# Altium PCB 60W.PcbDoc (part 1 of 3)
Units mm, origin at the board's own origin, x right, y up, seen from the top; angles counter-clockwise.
Board outline 118.9 x 83.5 mm, 3 copper layers (Top Layer, Mid-Layer 2, Bottom Layer); 99 components, 61 nets, 240 pads, 0 vias.
Unrouted connection lines stored in the file: 1.
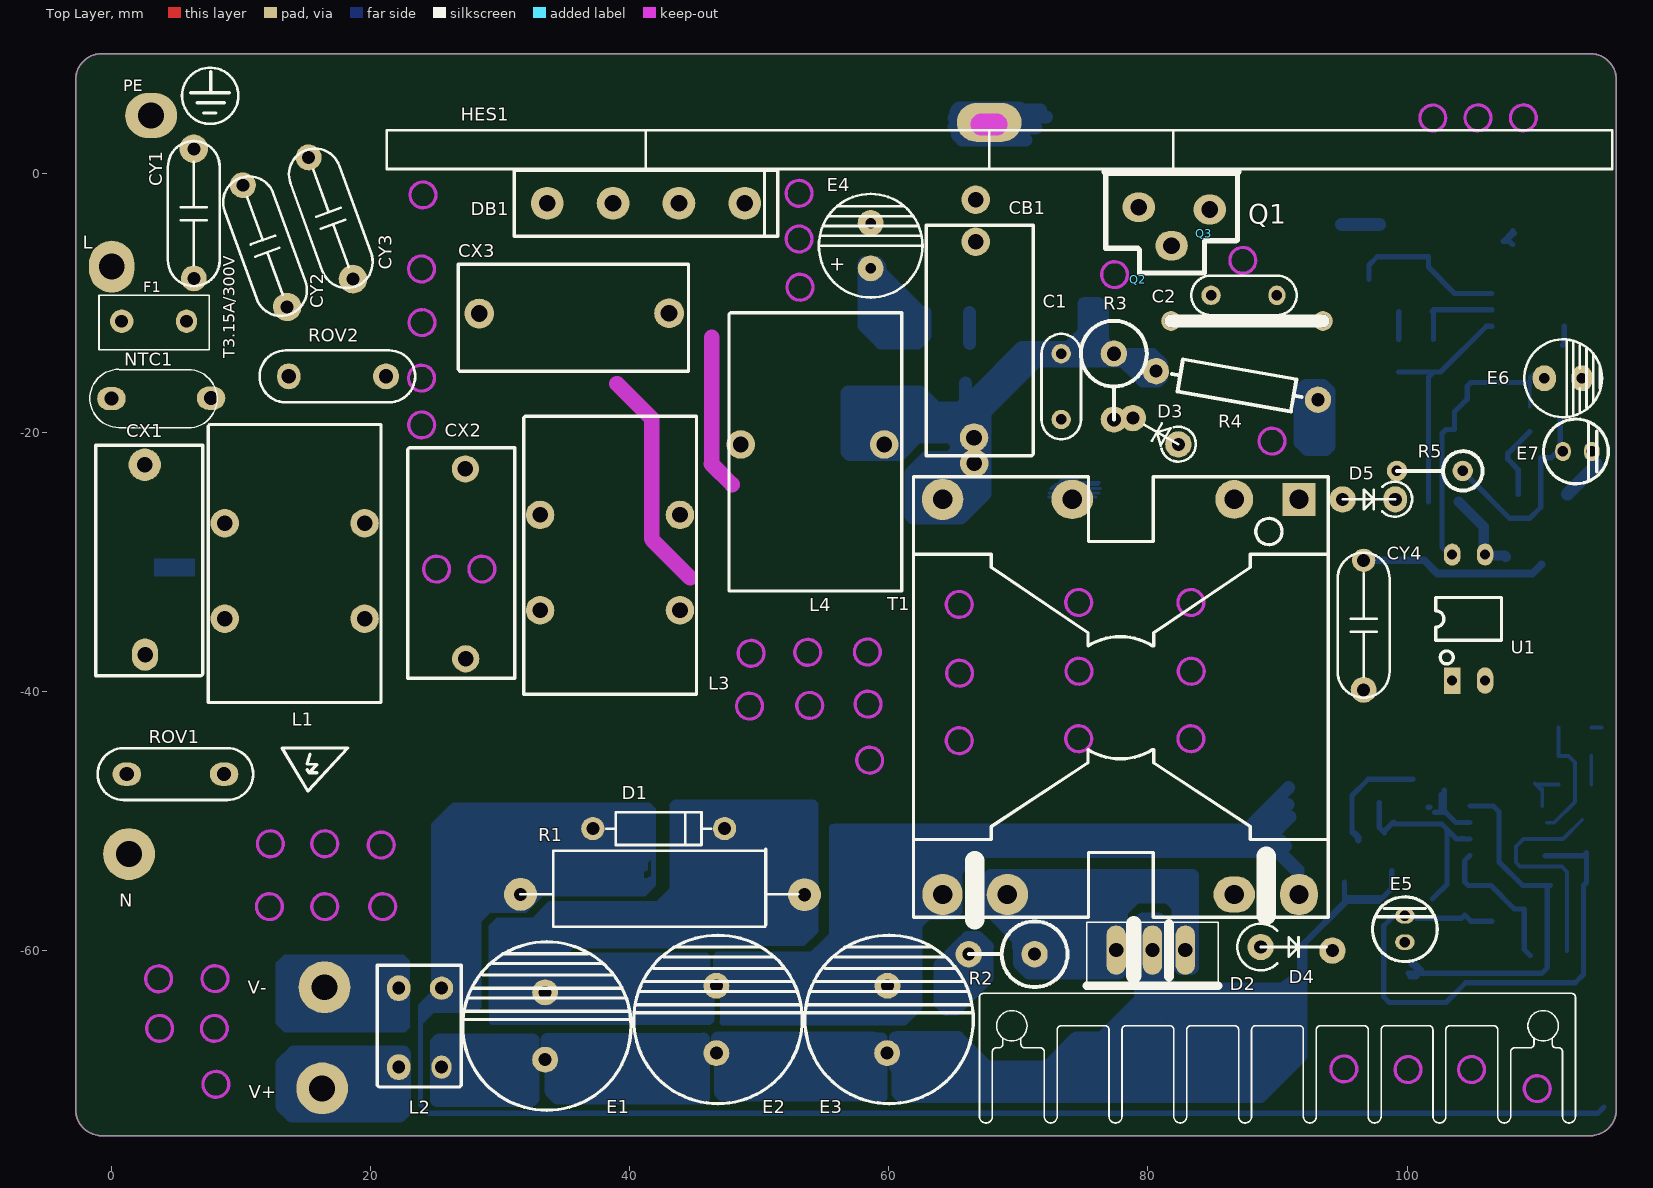
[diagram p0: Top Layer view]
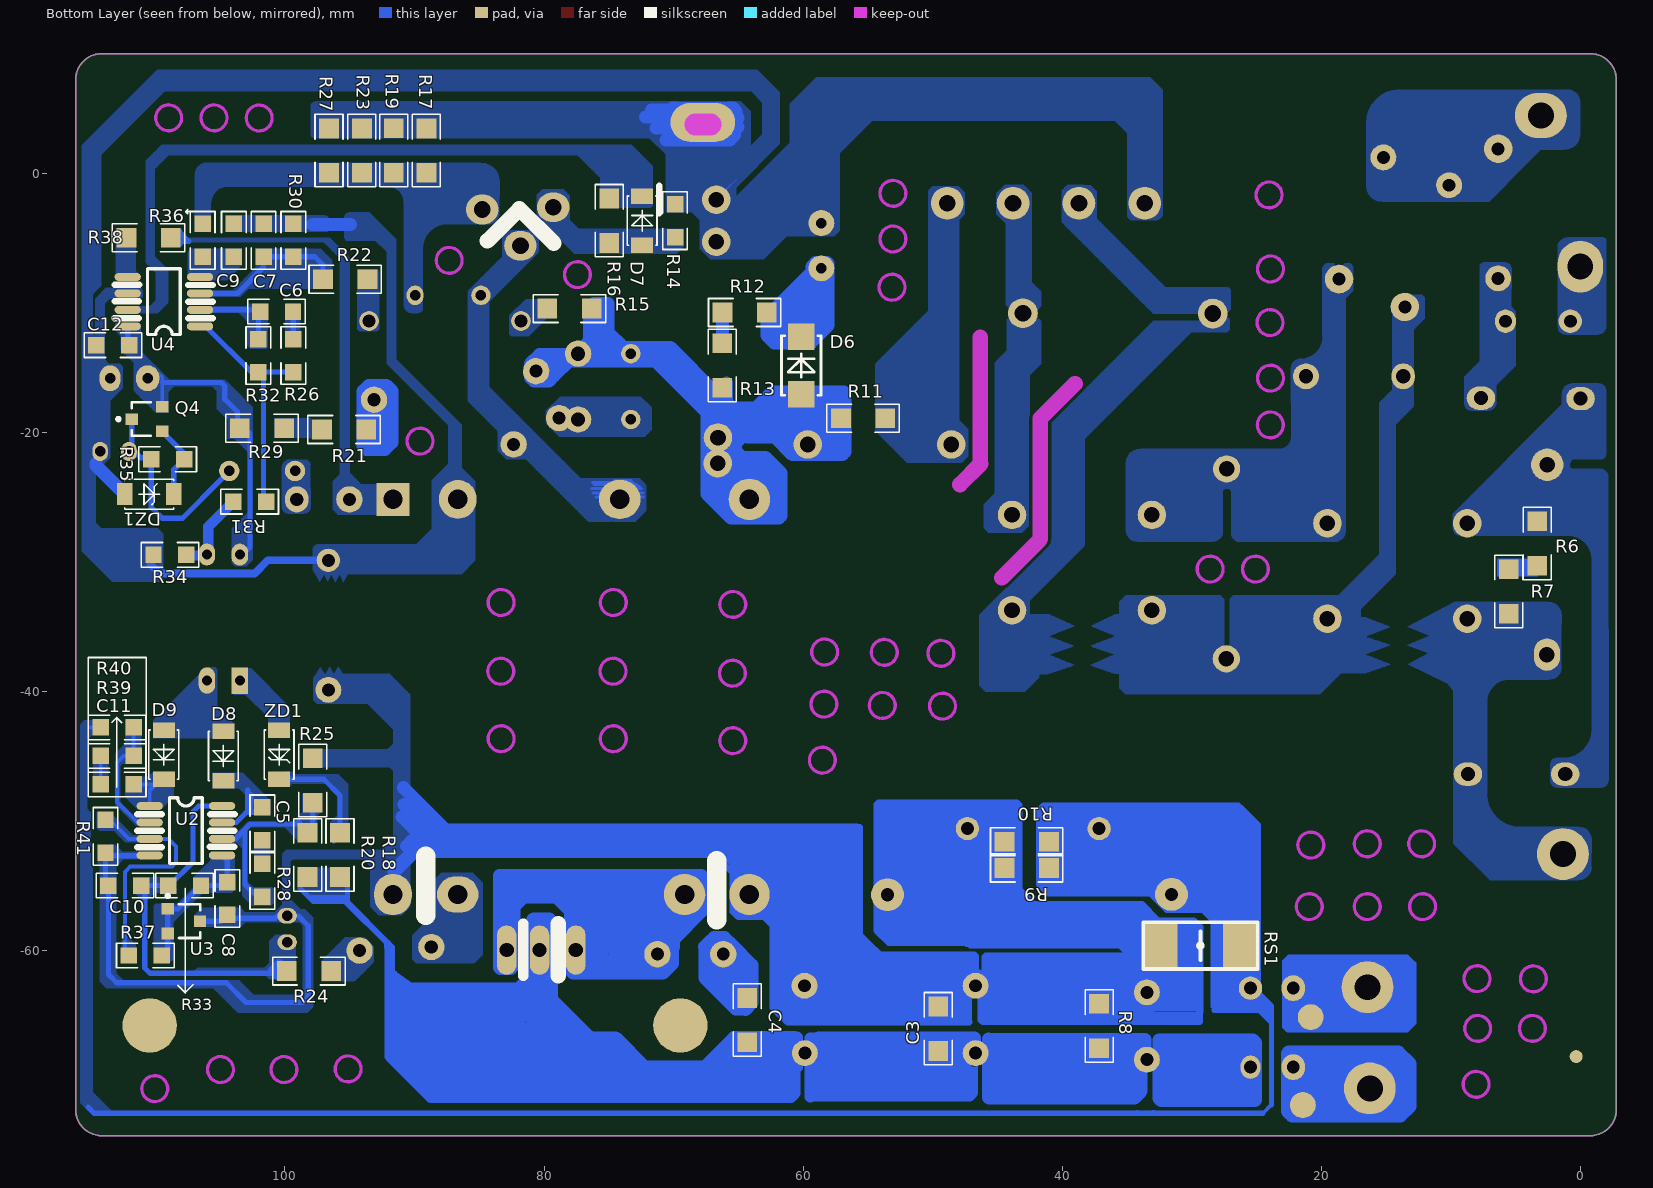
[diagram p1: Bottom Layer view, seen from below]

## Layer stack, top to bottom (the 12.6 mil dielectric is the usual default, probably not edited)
Top Layer: signal copper 0.0356
Dielectric: dielectric 0.32, FR-4, Dk 4.8
Mid-Layer 2: signal copper 0.0356
Dielectric: dielectric 0.32, FR-4, Dk 4.8
Bottom Layer: signal copper 0.0356

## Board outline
-2.75,-72.25 -2.75,7.25 cw(c-0.75,7.25) -0.75,9.25 114.15,9.25 cw(c114.15,7.25) 116.15,7.25 116.15,-72.25 cw(c114.15,-72.25) 114.15,-74.25 -0.75,-74.25 cw(c-0.75,-72.25)

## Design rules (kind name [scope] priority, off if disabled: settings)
Clearance [All] p1: gap=0.254
PolygonConnect [All] p1: connectstyle=Direct reliefconductorwidth=0.254 reliefentries=4 polygonreliefangle="90 Angle"
RoutingVias [All] p1: holewidth=0.711 width=1.27 viastyle="Through Hole" minholewidth=0.711 minwidth=1.27 maxholewidth=0.711 maxwidth=1.27
SilkscreenOverComponentPads [All] p1: minsilkscreentomaskgap=0.254
SolderMaskExpansion [All] p1: expansion=0.102
TestPointUsage [All] p1: valid=0 allowmultiple=FALSE
Testpoint [All] p1: side=15 testpointundercomponent=TRUE minsize=1.016 maxsize=2.54 preferedsize=1.524 minholesize=0 maxholesize=1.016 preferedholesize=0.813 testpointgrid=0.025 style=1023 order=0123456789
Width [All] p1: maxlimit=7.62 minlimit=0.254 preferedwidth=0.254 toplayer_prefwidth=0.406 midlayer2_maxwidth=0.254 bottomlayer_prefwidth=0.406 minimp=50.000000 maximp=50.000000 favimp=50.000000
23 further rules are at their usual default settings.

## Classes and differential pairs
component class PD0020: C3 C4 C5 C6 C7 C8 C9 C10 C11 C12 CY3 CY4 D2 D3 D4 D5 D7 D8 D9 DB1 DZ1 E2 E3 E5 E6 E7 F1 L2 L3 NTC1 Q1 R1 R2 R3 R5 R6 R7 R8 R9 R14 R15 R16 R17 R18 R20 R21 R22 R23 R25 R26 R27 R30 R31 R32 R33 R34 R36 R37 R38 R39 R40 R41 R47 ROV2 T1 U1 U2 U3 U4 ZD1

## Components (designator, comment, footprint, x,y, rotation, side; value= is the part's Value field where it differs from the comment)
C1 "103/1KV" CAP200#1 73.311,-13.9 r270 top (schematic designator C2)
C2 "103/1KV" CAP200#2 84.875,-9.4 r0 top
C3 "0.1uF/100V" 1206 49.588,-65.995 r90 bottom (schematic designator C10)
C4 "221/1KV" 1206 64.319,-65.335 r270 bottom (schematic designator C7)
C5 "0.1uF/50V" 0805 101.75,-50.18 r90 bottom (schematic designator C15)
C6 "0.1uF/50V" 0805 100.65,-10.65 r180 bottom
C7 "102" 0805 101.65,-5.15 r270 bottom (schematic designator C5)
C8 "0.1uF/50V" 0805 104.45,-55.95 r90 bottom (schematic designator C14)
C9 "68pf" 0805 103.944,-5.15 r90 bottom (schematic designator C16)
C10 "0.1uF/50V" 0805 112.35,-54.95 r0 bottom (schematic designator C12)
C11 "0.1uF/50V" 0805 112.95,-47.15 r180 bottom (schematic designator C13)
C12 "104" 0805 113.28,-13.25 r180 bottom (schematic designator C4)
CB1 "Comment" PCBComponent_1#1 71.152,-3.995 r270 top
CX1 "Comment" PCBComponent_1#2 7.05,-20.975 r270 top
CX2 "Comment" PCBComponent_1#3 22.88,-38.949 r90 top
CX3 "Comment" PCBComponent_1#4 44.55,-15.25 r180 top
CY1 "Cap" Y#1 6.375,-8.1 r90 top (schematic designator C21)
CY2 "Cap" Y#1 10.139,-0.897 r290 top (schematic designator C21)
CY3 "Cap" Y#1 15.217,1.253 r290 top (schematic designator C20)
CY4 "222/400VAC" Y#2 96.64,-29.84 r270 top (schematic designator CY1)
D1 "Comment" DIODE-0.4 42.247,-50.552 r0 top
D2 "3N80" TO220M 80.347,-59.933 r180 top (schematic designator Q1)
D3 "FR107" DO-41_120 82.35,-20.9 r150 top (schematic designator D1)
D4 "FR107" DO-15_200 88.704,-59.696 r0 top (schematic designator D5)
D5 "FR107" DO-41_160 95.025,-25.15 r0 top (schematic designator D2)
D6 "D" SMA214 60.154,-14.814 r90 bottom (schematic designator D3)
D7 "D" LL-34 72.434,-3.638 r90 bottom (schematic designator D3)
D8 "" LL-34 104.75,-44.95 r270 bottom (schematic designator D6)
D9 "D" LL-34 109.35,-44.85 r270 bottom (schematic designator D7)
DB1 "DF107" DB-L200 41.265,-2.292 r180 top locked
DZ1 "DIODE_ZENER" LL-34_Z 110.475,-24.75 r180 bottom
E1 "Comment" "PCBComponent_1 - duplicate4"#1 33.611,-65.792 r270 top
E2 "Comment" "PCBComponent_1 - duplicate4"#1 46.819,-65.284 r270 top
E3 "Comment" "PCBComponent_1 - duplicate4"#2 60.027,-65.284 r270 top
E4 "Comment" CE8 58.604,-5.569 r90 top
E5 "47uF/35V" CE05#1 99.834,-58.305 r90 top (schematic designator C11)
E6 "Comment" CE6 112.05,-15.8 r0 top
E7 "10UF/50V" CE05#2 113.05,-21.45 r0 top (schematic designator C3)
F1 "Comment" "FUSE 3.15A/300VAC" 3.3,-11.5 r90 top
HES1 "Comment" "HES1  97*50MM" 21.25,0.35 r0 top locked
L1 "20MH" PCBComponent_1#5 18.15,-19.364 r180 top (schematic designator L3)
L2 "Comment" "PCBComponent_1 - duplicate1" 27.007,-70.364 r90 top
L3 "20MH" PCBComponent_1#5 42.49,-18.726 r180 top
L4 "20MH" PCBComponent_1#6 58.337,-10.75 r180 top (schematic designator L3)
NTC1 "1A/10R" NTC 0,-17.375 r0 top
Q1 "Comment" T-220品字 81.829,-2.622 r0 top locked
Q2 "Comment" PCBComponent_1#7 79.255,-8.21 r270 top
Q3 "Comment" PCBComponent_1#7 84.335,-4.654 r270 top
Q4 "Comment" SOT23 110.65,-18.95 r90 bottom
R1 "0.1R" RESQ5W 31.579,-55.632 r0 top (schematic designator R28)
R2 "100R" RES200#1 71.254,-60.25 r180 top (schematic designator R21)
R3 "100K" RES200#2 77.375,-13.9 r270 top (schematic designator R1)
R4 "100K" RES500 80.616,-15.251 r350 top (schematic designator R1)
R5 "20R" RES200S 104.301,-22.95 r180 top (schematic designator R7)
R6 "1M" 1206 3.35,-28.55 r90 bottom (schematic designator R20)
R7 "1M" 1206 5.55,-32.25 r90 bottom (schematic designator R19)
R8 "res1" 1206 37.167,-65.792 r270 bottom (schematic designator R22)
R9 "OPEN" 1206 42.755,-53.6 r0 bottom (schematic designator R23)
R10 "OPEN" 1206 42.755,-51.568 r0 bottom (schematic designator R23)
R11 "res1" 1206 55.379,-18.878 r0 bottom (schematic designator R22)
R12 "res1" 1206 64.523,-10.725 r180 bottom (schematic designator R22)
R13 "res1" 1206 66.25,-14.814 r90 bottom (schematic designator R22)
R14 "1.5M" 0805 69.894,-3.638 r270 bottom (schematic designator R2)
R15 "1.5M" 1206 78.036,-10.42 r180 bottom (schematic designator R2)
R16 "res1" 1206 74.974,-3.638 r90 bottom (schematic designator R8)
R17 "3.6R" 1206 89.085,1.772 r270 bottom (schematic designator R16)
R18 "res1" 1206 95.75,-52.584 r270 bottom (schematic designator R22)
R19 "3.6R" 1206 91.599,1.772 r270 bottom (schematic designator R16)
R20 "120K" 1206 98.25,-52.584 r270 bottom (schematic designator R29)
R21 "1M" 1206 95.435,-19.75 r180 bottom (schematic designator R6)
R22 "1.5M" 1206 95.35,-8.15 r180 bottom (schematic designator R3)
R23 "3.6R" 1206 94.063,1.772 r270 bottom (schematic designator R18)
R24 "res1" 1206 98.15,-61.55 r180 bottom (schematic designator R22)
R25 "10K" 1206 97.85,-46.85 r270 bottom (schematic designator R32)
R26 "10K" 0805 99.35,-14.05 r90 bottom (schematic designator R11)
R27 "3.6R" 1206 96.603,1.772 r270 bottom (schematic designator R17)
R28 "4.7K" 0805 101.75,-54.55 r270 bottom (schematic designator R30)
R29 "1M" 1206 101.765,-19.65 r180 bottom (schematic designator R6)
R30 "20K" 0805 99.35,-5.15 r270 bottom (schematic designator R12)
R31 "20k" 0805 102.725,-25.325 r0 bottom (schematic designator R13)
R32 "OPEN" 0805 102.05,-14.05 r270 bottom (schematic designator R10)
R33 "10K" 0805 107.75,-54.95 r180 bottom (schematic designator R31)
R34 "1k" 0805 108.875,-29.425 r180 bottom (schematic designator R14)
R35 "1k" 0805 109.05,-22.05 r180 bottom (schematic designator R14)
R36 "100r" 0805 106.35,-5.15 r270 bottom (schematic designator R33)
R37 "25K" 0805 110.78,-60.35 r180 bottom (schematic designator R27)
R38 "51K" 1206 110.522,-4.95 r180 bottom (schematic designator R4)
R39 "4.7K" 0805 112.95,-44.95 r0 bottom (schematic designator R24)
R40 "1K" 0805 112.95,-42.75 r0 bottom (schematic designator R25)
R41 "1K" 0805 113.85,-51.15 r90 bottom (schematic designator R26)
ROV1 "RES2" 471KD10#1 4.95,-46.35 r180 top (schematic designator R?)
ROV2 "RES2" 471KD10#2 17.45,-15.65 r0 top (schematic designator R?)
RS1 "" 2512 32.349,-59.583 r270 bottom
T1 "T" T-PQ32L0606 77.909,-40.392 r270 top locked (schematic designator *)
U1 "PC817" DIP04 104.75,-34.375 r90 top (schematic designator U4)
U2 "LM358" SO-8 110.438,-48.81 r180 bottom
U3 "TL431" SOT-23 107.8,-57.7 r270 bottom
U4 "L6562" SO-8 106.55,-11.79 r0 bottom (schematic designator U?)
ZD1 "30V" LL-34_Z 100.45,-44.85 r270 bottom

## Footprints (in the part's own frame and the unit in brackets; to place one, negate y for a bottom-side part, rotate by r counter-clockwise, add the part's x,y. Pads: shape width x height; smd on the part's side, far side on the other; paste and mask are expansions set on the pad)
471KD10#1 [mm]
  oval 2.2x1.8 hole 1.1: 1(-3.75,0) 2(3.75,0)
  silkscreen extent -6,-2 6,2
471KD10#2 [mm]
  oval 1.8x2 hole 1.1: 1(-3.75,0)
  round 2 hole 1.1: 2(3.75,0)
  silkscreen extent -6,-2 6,2
0805 [mm]
  rect 1.27x1.27 smd: 1(-1.27,0) 2(1.27,0)
  silkscreen extent -2.22,-0.95 2.22,0.95
1206 [mil]
  rect 60x60 smd: 1(-67.51,0.02) 2(67.49,0.02)
  silkscreen extent -110,-43 110,43
2512 [mm]
  rect 3.3x2.5 smd: 1(0,0) 2(0,6)
  silkscreen extent -1.8,-1.4 1.8,7.4
CAP200#1 [mm]
  round 1.5 hole 0.813: 1(0,0) 2(5.08,0)
  silkscreen extent -1.52,-1.52 6.6,1.52
CAP200#2 [mm]
  round 1.5 hole 0.813: 1(0,0)
  oval 1.3x1.5 hole 0.813: 2(5.08,0)
  silkscreen extent -1.52,-1.52 6.6,1.52
CE05#1 [mm]
  oval 1.2x1.5 hole 0.813: 1(-1.016,0) 2(1.016,0)
  silkscreen extent -2.52,-2.5 2.48,2.5
CE05#2 [mm]
  oval 1.2x1.5 hole 0.813: 1(-1.016,0) 2(1.216,0)
  silkscreen extent -2.51,-2.5 2.48,2.5
CE6 [mm]
  oval 1.8x2 hole 0.813: 1(-1.45,0)
  oval 1.6x2 hole 0.813: 2(1.45,0)
  silkscreen extent -3,-3 3,3
CE8 [mm]
  round 2 hole 0.813: 1(-1.75,0) 2(1.75,0)
  silkscreen extent -4,-4 4,4
DB-L200 [mm]
  round 2.54 hole 1.3: 1(-7.62,0) 2(-2.54,0) 3(2.54,0) 4(7.62,0)
  silkscreen extent -10.16,-2.54 10.16,2.54
DIODE-0.4 [mm] "Tunnel Diode - Dependent Source Model; 2 Leads"
  round 1.8 hole 1: 1(-5.08,0) 2(5.08,0)
  silkscreen extent -4.06,-1.27 4.06,1.27
DIP04 [mil]
  rect 80x50 hole 30: 1(-187.4,50)
  oval 80x50 hole 30: 2(-187.4,-50)
  oval 66.93x50 hole 30: 3(195.83,-50.02) 4(195.28,49.98)
  silkscreen extent -65,-100 65,100
DO-15_200 [mil]
  round 80 hole 40: 1(0.02,0) 2(218.01,-10.98)
  silkscreen extent -71,-71 200,71
DO-41_120 [mil]
  round 80 hole 40: 1(0,0.01) 2(159.37,0)
  silkscreen extent -53,-54 120,53
DO-41_160 [mil]
  round 80 hole 40: 1(0,0)
  oval 70.87x80 hole 40: 2(160,0)
  silkscreen extent 0,-52 211,54
"FUSE 3.15A/300VAC" [mm]
  round 1.8 hole 1: 1(0.1,2.5)
  oval 1.8x1.6 hole 1: 2(0.1,-2.5)
  silkscreen extent -2.1,-4.25 2.1,4.25
"HES1  97*50MM" [mm]
  oval 5x3 all layers, no hole: 0(46.5,3.6)
  silkscreen extent 0,0 94.58,3
LL-34 [mm]
  rect 1.2x1.7 smd: 1(-1.9,0) 2(1.9,0)
  silkscreen extent -1.9,-1.15 1.9,1.15
LL-34_Z [mm]
  rect 1.2x1.7 smd: 1(-1.9,0) 2(1.9,0)
  silkscreen extent -1.9,-1.15 1.9,1.15
NTC [mm]
  oval 2.2x1.8 hole 1.1: 1(0.01,0.01) 2(7.694,0.045)
  silkscreen extent -1.65,-2.26 8.16,2.27
PCBComponent_1#1 [mm]
  round 2.2 hole 1.2: 0(1.269,-4.445) 1(16.383,-4.572)
  silkscreen extent 0,-8.25 17.78,0
PCBComponent_1#2 [mm]
  round 2.5 hole 1.2: 0(1.499,-4.47)
  oval 2.5x2 hole 1.2: 1(16.155,-4.445)
  silkscreen extent 0,-8.25 17.78,0
PCBComponent_1#3 [mm]
  round 2.1 hole 1.2: 0(1.499,-4.47) 1(16.154,-4.444)
  silkscreen extent 0,-8.25 17.78,0
PCBComponent_1#4 [mm]
  round 2.3 hole 1.3: 0(1.499,-4.47) 1(16.155,-4.445)
  silkscreen extent 0,-8.25 17.78,0
PCBComponent_1#5 [mm]
  round 2.2 hole 1.2: 1(-1.397,7.62) 2(9.398,7.62) 3(9.398,14.986) 4(-1.397,14.986)
  silkscreen extent -2.67,0 10.67,21.46
PCBComponent_1#6 [mm]
  round 2.2 hole 1.2: 1(-1.321,10.16) 2(9.753,10.16)
  silkscreen extent -2.67,0 10.67,21.46
PCBComponent_1#7 [mm]
"PCBComponent_1 - duplicate1" [mm]
  oval 2x1.8 hole 1: 0(1.397,4.826) 3(7.493,4.826)
  oval 1.8x1.53 hole 1: 1(1.397,1.524)
  round 1.8 hole 1: 2(7.493,1.524)
  silkscreen extent -0.13,0 9.27,6.48
"PCBComponent_1 - duplicate4"#1 [mm]
  round 2 hole 1: 0(-2.6,-0.127) 1(2.6,-0.127)
  silkscreen extent -6.5,-6.5 6.5,6.5
"PCBComponent_1 - duplicate4"#2 [mm]
  round 2 hole 1: 0(-2.6,-0.127) 1(2.6,-0.152)
  silkscreen extent -6.5,-6.5 6.5,6.5
RES200#1 [mil]
  round 80 hole 39.37: 1(0,0.01) 2(199.99,0)
  silkscreen extent -100,-100 200,100
RES200#2 [mil]
  round 80 hole 43.31: 1(0,0) 2(200,0)
  silkscreen extent -100,-100 200,100
RES200S [mm]
  round 1.575 hole 0.813: 1(0,0) 2(5.08,0)
  silkscreen extent -1.52,-1.52 5.08,1.52
RES500 [mil]
  round 80 hole 40: 1(0,0) 2(500,0)
  silkscreen extent 50,-50 450,50
RESQ5W [mm]
  round 2.54 hole 1.016: 1(0,0) 2(21.92,-0.025)
  silkscreen extent 0,-2.5 21.44,3.35
SMA214 [mil]
  rect 80x80 smd: 1(-87.5,0) 2(87.5,0)
  silkscreen extent -90,-60 90,60
SO-8 [mm]
  oval 2.032x0.61 smd: 1(0,0) 2(0,-1.27) 3(0,-2.54) 4(0,-3.81) 5(5.588,-3.81) 6(5.588,-2.54) 7(5.588,-1.27) 8(5.588,0)
  silkscreen extent 1.52,-4.45 4.06,0.63
SOT23 [mm] "SOT-23; 3 Leads; Body 3.1 x 2.5 mm, inc. leads (LxW max), Alternate Lead Configuration"
  rect 0.9x0.95 smd: 1(0,1.175) 2(0.95,-1.175) 3(-0.95,-1.175)
  silkscreen extent -1.3,-0.3 1.3,2.33
SOT-23 [mm] "SOT-23; 3 Leads; Body 3.0 x 2.6 mm, inc. leads (LxW max)"
  rect 0.9x0.95 smd: 1(-0.95,-1.25) 2(0.95,-1.25) 3(0,1.25)
  silkscreen extent -2.07,-1.38 1.3,1.25
T-220品字 [mm]
  oval 2.5x2.3 hole 1.3: 1(-2.54,0.025) 2(2.946,-0.152) 3(0,-2.946)
  silkscreen extent -5.11,-5.08 5.08,2.77
T-PQ32L0606 [mm]
  rect 2.54x2.54 hole 1.5: 1(-15.25,13.75)
  oval 3x2.9 hole 1.5: 2(-15.25,8.75)
  oval 3x3.2 hole 1.5: 4(-15.25,-3.75)
  round 3.2 hole 1.5: 6(-15.25,-13.75) 8(15.25,-8.75)
  oval 3.2x3.1 hole 1.5: 7(15.25,-13.75)
  oval 2.8x3.2 hole 1.5: 11(15.25,8.75)
  oval 3.2x2.9 hole 1.5: 12(15.25,13.75)
  silkscreen extent -17,-16 17,16
TO220M [mm]
  oval 1.5x3.81 hole 1.1: 1(-2.54,0) 2(0,0) 3(2.794,0)
  silkscreen extent -5.08,-2.16 5.08,2.74
Y#1 [mm]
  round 2 hole 1: 1(0.01,0.01)
  round 2.2 hole 1: 2(10.01,0.01)
  silkscreen extent -0.59,-1.99 10.61,2.01
Y#2 [mm]
  round 1.8 hole 1: 1(0.01,0.01)
  round 2 hole 1: 2(10.01,0.01)
  silkscreen extent -0.59,-1.99 10.61,2.01

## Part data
C1 C2 C3 C4 C5 C6 C8 C9 C10 C11 CY4: library part CAP, "Capacitor"
C7 C12: library part cap, "无极电容"
CY1 CY2 CY3: "Capacitor"
D2: library part "MOSFET N", "场效应管"
D3 D4: library part DIODE, "Diode"
D5 D8 ZD1: library part D, "二极管"
D6 D7 D9: "二极管"
DB1: library part BRIDGE2, "Diode Bridge"
E5: library part ELECTRO1, "Electrolytic Capacitor"
E7: library part CE, "电解电容"
L1 L3 L4: library part L2C
NTC1: library part VARISTOR
R1: library part Res1, "Resistor"
R2 R5 R6 R7 R9 R10 R14 R15 R17 R19 R20 R21 R22 R23 R25 R26 R27 R28 R29 R30 R31 R32 R33 R34 R35 R36 R37 R38 R39 R40 R41: library part res1, "Resistor"
R3 R4: library part RES2
R8 R11 R12 R13 R16 R18 R24: "Resistor"
U1: "光电耦合器"

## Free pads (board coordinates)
  round 1 smd far side: 0(0.35,-68.15)
  round 2.2 hole 1.2: 0(66.605,-22.358) 1(66.707,-2.013)
  oval 5x3 smd far side: 0(67.75,3.95)
  round 4.2 smd far side: 0(69.476,-65.75) 1(110.446,-65.75)
  round 1.524 hole 1: 0(81.79,-11.38) 1(93.51,-11.38)
  round 4 hole 2: 2(1.375,-52.525) 2(16.275,-70.6) 2(16.45,-62.8)
  oval 4x3.5 hole 2: 2(3.072,4.475)
  oval 3.5x4 hole 2: 3(0.031,-7.183)
  round 2 smd far side: 3(20.835,-65.106) 3(21.444,-71.888)

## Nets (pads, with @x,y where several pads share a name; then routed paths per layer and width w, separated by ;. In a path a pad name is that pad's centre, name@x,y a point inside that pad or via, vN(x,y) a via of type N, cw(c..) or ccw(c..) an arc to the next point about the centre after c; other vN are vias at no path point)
C6_2: C6.2 R26.2 | length 2.1
  Bottom Layer w0.406: R26.2@99.35,-12.78 99.35,-10.68 C6.2@99.38,-10.65
C15_1: C5.1 R28.1
CX4_0: CX1.0 L1.2 NTC1.1 R6.2 ROV1.2
CY1_2: CX2.0 CY2.2 L1.4 L3.3 ROV2.1
CY2_2: CX2.1 CY3.2 L1.1 L3.2 ROV2.2 | length 1.1
  Bottom Layer w0.254: CY3.2@18.65,-8.15 CY3.2@18.65,-7.1
D2_1: D5.1 R38.2 T1.1 | length 2.5
  Bottom Layer w0.406: 107.425,-5.225 108.15,-4.5 R38.2@108.15,-4.425 ; 107.6,-5.225 107.65,-5.225 R38.2@108.275,-4.6 ; 107.75,-5.225 107.9,-5.225 R38.2@108.15,-5.475
D2_2: D5.2 R5.2
D5_2: D4.2 R24.2
DB1_1: DB1.1 L4.2 R11.1
DB1_2: CX3.0 DB1.2 L3.1
DB1_3: CX3.1 DB1.3 L3.4
Dorian: C1.2 D3.2 R3.2
F1_2: CY1.1 F1.2 NTC1.2
GND: C7.1 C9.2 C12.1 CB1.0 CY4.1 DB1.4 DZ1.1 E4.2 E6.2 E7.2 HES1.0 pad.1@66.707,-2.013 R14.1 R17.1 R19.1 R23.1 R27.1 R30.1 R34.1 T1.2 U4.6 | length 51.2
  Bottom Layer w0.6: CY4.1@96.65,-29.85 101.33,-29.85 102.354,-30.874 109.656,-30.874 110.35,-30.18 110.38,-30.18
  Bottom Layer w1: 65.021,3.606 65.123,3.505 67.75,3.505 71.357,3.505 ; 65.021,4.294 65.087,4.359 67.75,4.359 72.183,4.359 ; 65.203,4.777 65.345,4.919 67.75,4.919 71.727,4.919 ; 65.285,2.971 65.652,2.603 67.75,2.603 70.607,2.603 ; 65.285,4.929 65.418,5.063 67.75,5.063 70.106,5.063 ; 94.95,-3.95 97.88,-3.95 ; DZ1.1@112.375,-24.75 114.6,-22.525 114.6,-22.38
L: F1.1 pad.3@0.031,-7.183
L4_0: L2.0 pad.2@16.275,-70.6 pad.3@21.444,-71.888 | length 44.2
  Bottom Layer w0.4: 14.633,-68.967 16.275,-68.967 17.914,-68.967 L2.0@22.181,-68.967
  Bottom Layer w1: L2.0@22.486,-68.459 22.486,-68.967 22.486,-71.888 22.486,-72.523 ; 17.939,-67.799 14.053,-67.799 13.164,-68.688 13.164,-71.99 13.9,-72.726 16.275,-72.726 18.168,-72.726 ; 17.939,-67.799 22.181,-67.799 22.537,-67.799 22.638,-67.9 22.638,-68.967 22.638,-71.888 22.638,-72.371 22.486,-72.523 ; 17.939,-67.799 17.914,-67.824 17.914,-68.967 17.914,-70.6 17.914,-72.472 18.168,-72.726 ; 18.168,-72.726 21.444,-72.726 22.283,-72.726 22.486,-72.523
L4_1: C3.1 C4.2 D2.2 E1.1 E2.1 E3.1 L2.1 R8.2 R18.2 R20.2 | length 526.7
  Bottom Layer w0.127: 46.59,-69.729 46.59,-69.145 ; E2.1@46.59,-68.459 46.59,-68.941 ; 46.615,-68.967 46.768,-68.967 46.59,-69.145 ; E2.1@46.793,-68.738 46.59,-68.941 ; 46.59,-69.145 46.59,-68.941
  Bottom Layer w0.3: D2.2@80.906,-61.375 82.478,-62.947 82.675,-62.947 ; 81.973,-63.074 81.175,-62.277 81.175,-62.2 81.425,-62.2 82.05,-62.825
  Bottom Layer w0.4: L2.1@25.483,-68.967 32.544,-68.967 32.909,-68.967 E1.1@33.484,-68.392 34.369,-67.507 R8.2@37.167,-67.507 42.12,-67.507 45.701,-67.507 E2.1@46.325,-67.507 ; E2.1@46.692,-67.884 46.768,-67.884 49.588,-67.884 59.468,-67.884 E3.1@59.875,-67.884 60.484,-67.884 63.485,-67.884 C4.2@64.15,-67.219 ; C4.2@64.15,-67.175 C4.2@64.15,-67.219 ; C4.2@64.319,-67.05 C4.2@64.15,-67.219 ; D2.2@80.347,-59.188 D2.2@80.347,-59.933 80.347,-63.925 ; R18.2@95.175,-54.675 95.175,-55.875 ; 95.308,-56.165 97.835,-56.165 98.825,-55.175 98.825,-54.299 R20.2@98.825,-53.8 ; 97.9,-55.875 95.175,-55.875 ; C4.2@64.15,-67.219 64.15,-67.775 65.5,-69.125 78.675,-69.125 80.347,-67.453 80.347,-66.122 80.347,-65.817 80.347,-65.157 80.347,-64.7 80.347,-63.925 ; 80.347,-63.925 80.734,-64.312 80.963,-64.541 81.147,-64.725 81.439,-64.725 81.744,-64.725 84.208,-64.725 84.843,-64.725 85.503,-64.725 86.164,-64.725 86.494,-64.725 86.873,-64.725 90.101,-64.725 90.477,-64.725 91.879,-63.324 92.082,-63.12 92.082,-62.668 92.082,-59.721 92.082,-59.391 92.107,-59.366 95.175,-56.298 95.175,-55.875
  Bottom Layer w0.508: 78.391,-66.656 79.061,-65.986 ; 79.814,-66.656 80.347,-66.122 81.744,-64.725 81.973,-64.497 81.973,-64.192 ; 80.779,-66.376 81.388,-65.767 ; 80.906,-63.303 81.058,-63.455 81.515,-63.455 81.592,-63.455 ; 81.388,-67.849 81.82,-67.418 81.846,-67.392 81.973,-67.265 ; 81.973,-63.252 81.973,-63.455 ; 81.973,-63.074 81.592,-63.455 ; 82.43,-68.713 82.608,-68.535 ; 82.608,-65.665 84.843,-65.665 85.148,-65.665 85.503,-65.665 86.164,-65.665 86.849,-65.665 87.154,-65.665 87.637,-65.665 88.653,-65.665 89.161,-65.665 90.101,-64.725 90.426,-64.4 91.498,-63.328 91.752,-63.074 91.752,-62.617 91.752,-62.338 ; 83.446,-70.745 82.887,-70.745 83.801,-69.831 84.03,-69.602 84.182,-69.602 ; 83.776,-71.329 83.827,-71.278 84.182,-70.923 ; 84.157,-70.745 84.182,-70.72 ; 91.391,-63.811 91.879,-63.324 91.879,-62.465 ; 91.421,-62.719 91.193,-62.947 90.685,-63.455 81.973,-63.455 ; 92.082,-64.319 92.082,-63.12 92.082,-62.668 ; 95.308,-56.165 95.175,-56.298 92.107,-59.366 ; 79.061,-65.986 79.687,-65.986 ; 79.061,-65.986 80.347,-64.7 80.734,-64.312 81.553,-63.493 81.592,-63.455 ; 79.687,-65.986 80.178,-65.986 80.347,-65.817 81.439,-64.725 81.973,-64.192 ; 79.687,-65.986 80.195,-65.478 80.195,-65.309 80.347,-65.157 80.963,-64.541 81.428,-64.076 81.973,-64.076 ; 81.592,-63.455 81.973,-63.455 ; 81.973,-64.192 82.088,-64.076 81.973,-64.076 ; 81.973,-64.192 81.973,-64.076 ; 81.973,-64.076 81.973,-63.912 81.973,-63.455 ; 91.752,-62.338 91.879,-62.465 ; 91.752,-62.338 91.752,-61.944 91.752,-59.721 91.879,-59.594 ; 91.879,-62.465 92.082,-62.668 ; 91.879,-62.465 91.879,-59.594 ; 91.879,-59.594 92.082,-59.391 92.107,-59.366 ; 92.082,-62.668 92.082,-59.721 92.107,-59.696 92.107,-59.366
  Bottom Layer w0.9: 46.971,-69.348 46.971,-70.948 47.175,-71.151 59.367,-71.151 59.468,-71.253 59.468,-67.884 59.468,-66.732 55.201,-66.732 ; 60.484,-68.967 60.484,-67.884 60.484,-66.681 60.687,-66.681 ; 60.662,-69.374 60.662,-70.973 60.967,-71.278 83.827,-71.278 ; 84.182,-70.923 83.827,-71.278 ; 84.182,-64.7 84.208,-64.725 84.843,-65.36 ; 84.767,-63.785 84.843,-63.862 84.843,-64.725 84.843,-65.36 ; 86.773,-69.399 87.078,-69.094 ; 88.348,-64.141 88.983,-64.141 89.212,-63.912 ; 88.424,-65.665 88.653,-65.665 ; 88.678,-63.912 89.212,-63.912 ; 88.932,-65.665 88.653,-65.665 ; 91.447,-67.57 91.447,-67.824 89.542,-69.729 89.542,-68.891 91.447,-66.986 91.193,-66.986 88.983,-69.196 ; 91.498,-63.201 91.498,-63.328 90.426,-64.4 90.426,-64.273 90.304,-64.395 90.151,-64.395 ; 83.827,-71.278 88.729,-71.278 91.879,-68.129 91.879,-63.324 90.477,-64.725 87.408,-67.794 ; 84.843,-67.418 83.344,-67.418 81.82,-67.418 81.236,-67.418 81.261,-67.392 81.846,-67.392 83.344,-67.392 84.843,-67.392 ; 84.843,-67.418 85.503,-67.418 ; 84.843,-67.418 84.843,-68.916 84.868,-68.942 ; 84.843,-67.418 84.843,-67.392 ; 84.843,-67.392 85.021,-67.392 85.503,-66.91 ; 84.843,-67.392 84.843,-65.665 84.843,-65.36 ; 84.843,-65.36 85.148,-65.665 85.503,-66.021 ; 84.868,-69.272 84.741,-69.272 84.589,-69.424 84.386,-69.424 84.868,-68.942 ; 84.868,-69.272 85.097,-69.272 84.919,-69.45 84.919,-69.856 84.868,-69.907 84.868,-69.272 ; 84.868,-69.272 84.868,-68.942 ; 84.868,-68.942 84.919,-68.891 86.011,-68.891 86.824,-68.078 86.824,-67.494 ; 85.503,-67.418 86.164,-67.418 86.532,-67.049 ; 85.503,-67.418 85.503,-67.799 85.097,-68.205 85.656,-68.205 85.96,-67.9 86.418,-67.9 86.824,-67.494 ; 85.503,-67.418 85.503,-66.91 ; 85.503,-66.91 85.503,-66.021 ; 85.503,-66.91 85.948,-66.465 ; 85.503,-66.021 85.503,-65.665 85.503,-64.725 85.503,-63.684 85.668,-63.519 86.873,-64.725 87.637,-65.489 87.637,-65.665 87.637,-66.681 ; 85.503,-66.021 85.948,-66.465 ; 85.948,-66.465 86.164,-66.249 ; 85.948,-66.465 86.164,-66.681 ; 86.164,-66.681 86.506,-67.024 ; 86.164,-66.681 86.164,-67.265 86.037,-67.392 86.138,-67.392 86.506,-67.024 ; 86.164,-66.681 86.164,-66.249 ; 86.164,-66.249 86.684,-65.729 ; 86.164,-66.249 86.164,-65.665 86.164,-64.725 86.164,-64.395 86.494,-64.725 86.849,-65.081 86.849,-65.665 86.849,-65.894 86.684,-65.729 ; 86.506,-67.024 86.799,-66.732 86.799,-66.554 86.913,-66.668 ; 86.506,-67.024 86.532,-67.049 ; 86.532,-67.049 86.913,-66.668 ; 86.532,-67.049 86.824,-67.341 86.824,-67.494 ; 86.684,-65.729 86.697,-65.716 86.672,-65.716 86.684,-65.729 ; 86.824,-67.494 87.408,-66.91 ; 86.913,-66.668 87.154,-66.427 87.154,-65.665 87.408,-65.919 87.408,-66.783 ; 86.913,-66.668 86.926,-66.681 87.307,-66.681 87.408,-66.783 ; 87.078,-69.094 86.418,-69.094 85.783,-69.729 87.916,-69.729 88.627,-70.44 84.762,-70.44 87.408,-67.794 ; 87.078,-69.094 88.221,-69.094 ; 87.078,-69.094 87.408,-68.764 ; 87.408,-68.764 91.498,-64.674 91.498,-66.148 88.983,-68.662 ; 87.408,-68.764 87.408,-67.794 ; 87.408,-67.794 87.408,-66.91 ; 87.408,-66.91 87.472,-66.846 ; 87.408,-66.91 87.408,-66.783 ; 87.408,-66.783 87.472,-66.846 ; 87.472,-66.846 87.637,-66.681 ; 87.472,-66.846 87.637,-67.011 87.637,-66.681 ; 87.637,-66.681 88.653,-65.665 ; 88.221,-69.094 88.551,-69.094 ; 88.221,-69.094 91.193,-66.122 91.193,-66.402 88.983,-68.611 88.983,-68.662 ; 88.551,-69.094 88.881,-69.094 88.983,-69.196 ; 88.551,-69.094 88.17,-69.475 88.551,-69.475 89.237,-70.161 89.237,-69.45 88.983,-69.196 ; 88.551,-69.094 88.983,-68.662 ; 88.983,-69.196 88.983,-68.662 ; 89.212,-63.912 89.669,-63.912 ; 89.212,-63.912 89.313,-63.811 89.77,-63.811 89.669,-63.912 ; 89.669,-63.912 90.736,-63.912 90.786,-63.963 90.583,-63.963 90.151,-64.395 ; 89.669,-63.912 89.262,-64.319 89.262,-64.649 89.516,-64.395 90.151,-64.395
  Bottom Layer w1: E1.1@33.56,-68.104 33.611,-68.053 E1.1@33.611,-67.748 ; E1.1@33.636,-67.773 E1.1@33.611,-67.748 ; 33.916,-69.577 33.916,-70.821 34.449,-71.355 42.12,-71.355 ; E2.1@46.819,-68.332 46.768,-68.281 46.768,-67.884 46.768,-66.732 49.588,-66.732 58.833,-66.732 ; 60.687,-66.681 64.319,-66.681 65.335,-66.681 67.621,-68.967 72.219,-68.967 74.48,-66.706 76.461,-66.706 ; 76.105,-67.062 76.461,-66.706 ; 76.334,-66.681 76.486,-66.681 ; 76.842,-66.402 79.28,-63.963 ; 79.28,-64.344 79.28,-63.963 ; 79.509,-66.656 80.178,-65.986 80.347,-65.817 ; 79.737,-63.023 79.737,-63.43 79.433,-63.735 ; D2.2@80.017,-60.229 80.017,-63.227 ; D2.2@80.068,-59.467 80.068,-59.933 80.068,-63.176 80.017,-63.227 ; 80.195,-66.706 76.461,-66.706 ; D2.2@80.347,-59.188 D2.2@80.347,-59.933 80.347,-63.925 80.347,-64.7 80.347,-65.157 80.347,-65.817 ; D2.2@80.55,-61.118 80.55,-62.49 80.906,-62.846 ; 80.855,-66.656 81.439,-66.071 81.617,-66.071 ; 80.906,-63.862 80.906,-63.303 80.906,-62.846 ; 81.109,-67.214 81.973,-66.351 ; 81.973,-63.912 81.553,-63.493 81.515,-63.455 80.906,-62.846 ; 82.252,-62.947 82.478,-62.947 90.316,-62.947 ; 82.303,-63.862 82.088,-64.076 81.973,-64.192 81.439,-64.725 80.347,-65.817 ; 82.557,-69.399 83.192,-68.764 ; 82.633,-67.722 82.912,-68.002 ; 83.141,-66.427 83.344,-66.63 83.344,-67.392 83.344,-67.418 83.344,-68.611 ; 83.192,-67.976 83.192,-68.764 ; 83.598,-68.357 83.344,-68.611 ; 83.649,-70.135 83.801,-69.983 83.801,-69.831 83.801,-68.307 ; 89.963,-63.194 90.316,-62.947 ; 91.752,-62.617 91.574,-62.617 91.244,-62.947 91.193,-62.947 90.316,-62.947 ; 91.752,-61.944 90.316,-62.947 ; E1.1@33.611,-67.748 33.611,-66.833 37.167,-66.833 41.942,-66.833 ; 41.942,-66.833 42.12,-67.011 42.12,-67.507 42.12,-71.355 ; 41.942,-66.833 45.676,-66.833 45.701,-66.808 45.701,-67.507 45.701,-67.884 45.701,-71.304 45.651,-71.355 42.12,-71.355 ; 76.461,-66.706 76.486,-66.681 ; 76.486,-66.681 77.35,-66.681 79.788,-64.243 ; 76.486,-66.681 79.433,-63.735 ; 79.28,-63.963 79.433,-63.811 ; 79.433,-63.811 79.433,-63.735 ; 79.433,-63.811 79.788,-63.455 ; 79.433,-63.735 79.433,-59.933 79.433,-57.689 79.585,-57.537 79.788,-57.537 ; 79.788,-64.37 77.731,-66.427 78.086,-66.427 79.788,-64.725 79.788,-64.37 ; 79.788,-64.37 79.788,-64.243 ; 79.788,-64.243 80.017,-64.014 80.017,-63.227 ; 79.788,-64.243 79.788,-63.455 ; 79.788,-63.455 80.017,-63.227 ; 79.788,-63.455 79.788,-59.933 79.788,-57.537 ; 79.788,-57.537 80.347,-57.537 80.83,-57.537 80.906,-57.613 80.906,-59.933 80.906,-61.375 80.906,-62.846 ; 83.192,-68.764 83.344,-68.611 ; 83.192,-68.764 83.192,-69.983 83.344,-70.135 83.344,-68.611 ; 25.091,-71.496 25.153,-71.558 32.366,-71.558 32.544,-71.38 32.544,-68.967 32.544,-68.392 32.544,-66.884 25.28,-66.884 25.091,-67.073 25.091,-68.967 25.091,-71.496
L4_2: D1.1 L2.2 R1.1 R9.1 R10.1 R40.2 RS1.2 | length 281.2
  Bottom Layer w0.127: 28.175,-58.045 29.235,-56.985 ; 28.48,-57.638 28.607,-57.511 ; 28.607,-57.156 28.607,-57.511 ; 28.728,-57.277 28.728,-57.39 ; 29.15,-56.985 29.235,-56.985 ; 29.242,-56.648 29.242,-56.876 28.728,-57.39 ; 29.4,-56.985 29.235,-56.985 ; 29.496,-56.648 29.496,-56.724 29.235,-56.985 ; 28.607,-57.511 28.728,-57.39
  Bottom Layer w0.3: 24.518,-72.523 23.857,-71.863 23.857,-65.538 23.857,-65.157 24.873,-64.141 L2.2@25.331,-63.684 ; R40.2@114.22,-42.75 115.025,-42.75
  Bottom Layer w0.4: 23.857,-71.863 23.857,-65.538 ; 24.518,-72.523 34.17,-72.523 ; 25.102,-63.913 24.873,-64.141 ; 25.204,-57.258 25.204,-50.461 25.569,-50.095 ; L2.2@25.331,-62.719 L2.2@25.483,-62.871 ; 25.356,-64.04 25.102,-64.293 ; RS1.2@25.508,-58.477 25.569,-58.416 25.569,-50.095 ; RS1.2@25.915,-59.061 25.915,-49.536 25.966,-49.485 ; RS1.2@26.174,-58.065 26.174,-57.351 26.174,-56.927 ; 28.302,-64.573 24.95,-64.573 24.886,-64.509 ; 28.353,-64.268 28.328,-64.293 25.102,-64.293 ; 28.582,-56.877 28.607,-56.902 28.607,-57.156 ; 29.395,-56.851 31.579,-56.851 31.96,-56.851 32.379,-56.432 33.205,-55.607 34.043,-55.607 ; 30.385,-48.952 30.614,-48.723 ; R1.1@31.173,-56.648 29.496,-56.648 29.242,-56.648 29.115,-56.648 ; R1.1@31.452,-56.191 31.579,-56.191 32.062,-56.191 32.1,-56.153 32.443,-55.81 32.747,-55.81 33.611,-54.946 33.611,-54.895 ; 32.951,-72.472 33.052,-72.472 ; 33.814,-55.353 34.297,-55.353 ; 34.221,-72.472 34.17,-72.523 ; 41.383,-48.926 41.383,-49.079 41.51,-49.206 41.51,-51.568 41.51,-52.813 41.231,-53.092 41.231,-53.6 41.231,-53.676 41.155,-53.6 41.155,-51.568 41.155,-51.3 41.155,-48.723 ; 115.2,-72.05 114.727,-72.523 34.17,-72.523 ; 23.857,-65.538 23.857,-65.157 ; 23.857,-65.538 24.886,-64.509 ; 23.857,-65.157 23.857,-64.675 ; 23.857,-65.157 24.873,-64.141 ; 23.857,-64.675 23.857,-64.243 L2.2@24.873,-63.227 ; 23.857,-64.675 24.873,-63.659 ; 24.873,-64.293 24.873,-64.497 24.886,-64.509 ; 24.873,-64.293 24.873,-64.141 ; 24.873,-64.293 25.102,-64.293 ; 24.873,-64.141 24.873,-63.659 ; 24.873,-63.659 L2.2@24.873,-63.227 ; L2.2@24.873,-63.227 24.873,-62.871 24.873,-50.273 25.569,-49.577 ; 24.886,-64.509 25.102,-64.293 ; 25.569,-50.095 25.569,-49.577 ; 25.569,-49.577 26.174,-48.972 ; 26.174,-56.927 26.598,-56.927 28.379,-56.927 28.607,-57.156 ; 26.174,-56.927 26.174,-56.648 ; 26.174,-56.648 26.174,-48.972 ; 26.174,-56.648 26.877,-56.648 29.115,-56.648 ; 26.174,-48.972 26.423,-48.723 30.614,-48.723 ; 28.607,-57.156 29.115,-56.648 ; 30.614,-48.723 41.155,-48.723 ; 34.043,-55.607 41.104,-55.607 41.841,-54.87 41.841,-53.6 41.841,-51.568 41.841,-49.104 41.46,-48.723 41.155,-48.723 ; 34.043,-55.607 34.297,-55.353 ; 34.297,-55.353 41.206,-55.353 41.536,-55.022 41.536,-54.464 41.434,-54.565 40.977,-54.565 ; 40.977,-54.565 41.256,-54.845 41.155,-54.845 40.901,-55.099 40.901,-54.616 40.85,-54.565 40.977,-54.565 ; 40.977,-54.565 40.926,-54.514 40.926,-53.6 40.926,-51.568 40.926,-51.071 40.926,-48.952 41.155,-48.723
  Bottom Layer w0.508: L2.2@25.331,-63.684 25.331,-62.871 L2.2@25.331,-62.719 ; L2.2@25.483,-62.871 25.483,-60.542 26.395,-59.629 RS1.2@26.6,-59.425 ; RS1.2@26.15,-59.8 26.174,-59.776 26.174,-59.583 26.174,-57.351 26.598,-56.927 26.877,-56.648 27.893,-55.632 R1.1@31.579,-55.632 31.579,-52.171 33.198,-50.552 D1.1@37.167,-50.552 40.407,-50.552 40.926,-51.071 41.155,-51.3 41.155,-51.568 R9.1@41.155,-53.6
L4_3: L2.3 pad.2@16.45,-62.8 pad.3@20.835,-65.106 | length 59.3
  Bottom Layer w0.4: 13.443,-65.843 13.265,-65.665 13.265,-60.966 13.469,-60.763 13.646,-60.763 ; 14.675,-61.748 15.798,-62.871 16.45,-62.871 pad.2@17.609,-62.871 ; 18.015,-65.792 20.835,-65.792 22.511,-65.792 22.587,-65.868 22.587,-62.871 22.587,-60.61 ; L2.3@22.181,-62.871 pad.2@17.609,-62.871 ; pad.2@17.609,-62.871 17.609,-65.716 17.99,-66.097 ; pad.2@17.609,-62.871 17.609,-62.8 17.609,-60.61 17.761,-60.458 ; 17.761,-60.458 13.418,-60.458 12.884,-60.992 12.884,-65.564 13.418,-66.097 17.99,-66.097 ; 17.761,-60.458 22.486,-60.458 22.841,-60.814 22.841,-62.871 22.841,-65.843 22.587,-66.097 20.835,-66.097 17.99,-66.097
Lydian: D4.1 T1.11
N: CX1.1 L1.3 pad.2@1.375,-52.525 R7.1 ROV1.1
